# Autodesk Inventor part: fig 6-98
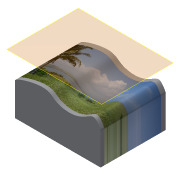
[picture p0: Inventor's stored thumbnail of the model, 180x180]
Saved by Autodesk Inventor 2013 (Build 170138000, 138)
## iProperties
Created: 2012-07
Part Number: fig 6-98
Material: Generic
Document SubType Name: Modeling
Designer: CADCIM
Density: 1 g/cm^3
Author: CADCIM
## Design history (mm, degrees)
sketch "Sketch1"
  geometry: L1 (0, 0)-(0, 12.146); L2 (32.23, 12.146)-(32.23, 0); L3 (32.23, 0)-(0, 0); 5 further points
  constraints: 6 end point, 1 parallel, 1 perpendicular, 1 vertical, 7 other
extrude "Extrusion1" new body sketch "Sketch1" distance "d0" = 24.5; taper "d1" = 0 deg
workplane "Work Plane1"
fillet "Fillet1" dims "d19" = 2
sketch "Sketch2"
  geometry: L1 (-33.343, 22.666)-(0.669, 22.666); L2 (0.669, 22.666)-(0.669, 1.409); L3 (0.669, 1.409)-(-33.343, 1.409); L4 (-33.343, 1.409)-(-33.343, 22.666); 1 other entity
  constraints: 2 other
feature "Decal1" sketch "Sketch2"
body "Solid1"
node "Image1"
other parameters: "d2" = 22
